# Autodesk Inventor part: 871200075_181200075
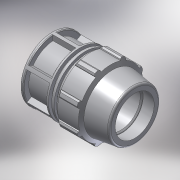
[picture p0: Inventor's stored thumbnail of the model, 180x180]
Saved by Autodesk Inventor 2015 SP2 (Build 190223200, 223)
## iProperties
Created: 2017-02
Part Number: 871200075_181200075
Material: PVC-Piping
Description: PLASSON END PLUG 75
Document SubType Name: Modeling
Designer: KIM
Mass: 92.6774 g
Surface Area: 199.44 cm^2
Volume: 66.1981 cm^3
Density: 1.4 g/cm^3
Appearance: Smooth - White
Author: Кирилл
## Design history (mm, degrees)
derived "87120.ipt"
feature "Solid1::87120.ipt"
tag "TaggingFeature1"
body "Solid1"
other parameters: "d2" = 75, "d4" = 25.28571, "d5" = 44.25, "d7" = 132, "d8" = 99, "d9" = 25.28571, "d11" = 5.05714, "d12" = 105.6, "d13" = 120 deg, "d14" = 97.5, "d15" = 8 deg, "d16" = 118.8, "d18" = 3.75, "d19" = 35 deg, "d20" = 17.5 deg, "d21" = 122.76, "d23" = 0, "d25" = 360 deg, "d27" = 2.64, "d34" = 6.6, "d36" = 0, "d42" = 44.25, "d43" = 3.96, "d46" = 2.25, "d53" = 1.5, "d55" = 360 deg, "d59" = 44.25, "d64" = 177, "d66" = 17.16, "d67" = 10.56, "d68" = 161, "d70" = 20.22857, "d71" = 5.05714, "d72" = 116.424, "d75" = 10.11429, "d_" = 75, "E_" = 132, "H_" = 177, "l_" = 161
